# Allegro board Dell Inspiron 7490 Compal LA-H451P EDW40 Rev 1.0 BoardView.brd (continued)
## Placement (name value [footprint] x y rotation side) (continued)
PR2  15K_0402_1%  [R_0402]  119.53 12.51 0 top
PR3  100K_0402_1%  [R_0402]  117.88 12.51 0 top
PR4  10K_0402_1%  [R_0402]  117.84 15.18 270 top
PR5  2.2K_0402_5%  [R_0402]  116.4 15.61 180 top
PR37  100_0402_5%  [R_0402]  107.91 9.87 270 top
PR39  200_0402_5%  [R_0402]  108.82 11.7 270 top
PR41  10K_0402_1%  [R_0402]  109.59 10.79 90 top
PR42  100_0402_5%  [R_0402]  107.14 9.87 270 top
PR101  10K_0402_5%  [R_0402]  98.44 25.92 0 top
PR102  0_0402_5%  [R0402_0OHM]  103.85 27.47 0 top
PR103  1M_0402_5%  [R_0402]  104.76 25.94 180 top
PR104  1M_0402_5%  [R_0402]  103.85 26.7 0 top
PR105  100K_0402_5%  [R_0402]  99.35 26.71 180 top
PR301  0_0402_5%  [R_0402]  13.98 12.6 270 bottom
PR302  499K_0402_1%  [R_0402]  10.4 18.07 90 bottom
PR303  150K_0402_1%  [R_0402]  11.19 18.07 90 bottom
PR304  10K_0402_1%  [R_0402]  11.21 16.94 270 bottom
PR305  4.7_1206_5%  [R_1206]  17.27 14.01 0 top
PR306  1K_0402_5%  [R_0402]  14.4 18.99 270 bottom
PR307  150K_0402_1%  [R_0402]  12.73 18.99 270 bottom
PR308  150K_0402_1%  [R_0402]  11.97 18.07 90 bottom
PR501  150K_0201_5%  [R_0201]  11.89 27.1 0 bottom
PR502  0_0201_5%  [R_0201]  10.77 20.64 0 bottom
PR503  0_0201_5%  [R0201_0OHM]  14.89 20.99 90 bottom
PR504  0_0603_5%  [R_0603]  15.79 21.39 270 bottom
PR505  0_0402_5%  [R_0402]  12.08 21.43 270 bottom
PR506  348K_0402_1%  [R_0402]  14.72 19.8 180 bottom
PR507  499_0402_1%  [R_0402]  13.65 20.54 90 bottom
PR508  19.6K_0402_1%  [R_0402]  12.86 20.44 90 bottom
PR509  10K_0201_1%  [R_0201]  14.32 21.52 270 bottom
PR510  4.7_0805_5%  [R_0805]  18.44 20.92 90 top
PR521  0_0402_5%  [R0402_0OHM]  50.41 5.89 90 top
PR522  0_0402_5%  [R0402_0OHM]  51.17 5.89 90 top
PR523  2.2K_0402_5%  [R_0402]  51.93 5.89 90 top
PR524  0_0402_5%  [R0402_0OHM]  45.87 7.51 270 top
PR525  1M_0402_5%  [R_0402]  50.9 7.64 0 top
PR1802  150K_0201_5%  [R_0201]  73.35 22.62 0 top
PR1803  0_0603_5%  [R_0603]  67.73 22.18 90 top
PR1804  274K_0402_1%  [R_0402]  67.09 21.2 270 top
PR1805  499_0402_1%  [R_0402]  67.93 20.26 0 top
PR1806  40.2K_0402_1%  [R_0402]  67.93 19.48 0 top
PR1807  20K_0402_1%  [R_0402]  68.9 18.67 180 top
PR1808  4.7_0805_5%  [R_0805]  69.68 28.43 0 top
PR1809  0_0402_5%  [R_0402]  68.16 17.88 180 top
PR1810  1M_0402_5%  [R_0402]  68.15 17.09 180 top
PR1813  0_0402_5%  [R_0402]  68.93 17.89 270 top
PR1814  100K_0201_5%  [R_0201]  73.93 22.05 180 top
PR1815  100K_0402_1%  [R_0402]  112.15 17.64 0 top
PRA01  0_0201_5%  [R_0201]  139.88 20.39 270 bottom
PRA02  4.7_1206_5%  [R_1206]  142.41 23.9 0 top
PRB01  0.01_1206_1%  [R_1206_4P-D]  184.67 16.12 270 top
PRB02  1_0402_1%  [R_0402]  194.06 18.58 90 bottom
PRB03  1_0402_1%  [R_0402]  196.66 19.09 90 bottom
PRB04  0_0603_5%  [R0603_0OHM]  192.48 16.32 90 bottom
PRB05  442K_0402_1%  [R_0402]  189.47 23.87 0 bottom
PRB06  3.3_0603_1%  [R_0603]  198.15 19.97 270 bottom
PRB07  100K_0402_5%  [R_0402]  190.39 23.11 180 bottom
PRB08  1_0805_5%  [R_0805]  188.86 19.47 0 bottom
PRB09  4.7_0402_5%  [R_0402]  200.11 19.96 0 bottom
PRB10  0_0402_5%  [R0402_0OHM]  192.85 23.43 180 bottom
PRB11  499K_0402_1%  [R_0402]  192.41 20.36 180 bottom
PRB12  0.005_1206_1%  [R_1206_4P-D]  93.15 15.9 270 top
PRB13  0_0402_5%  [R_0402]  192.3 22.25 180 bottom
PRB14  0_0402_5%  [R_0402]  192.85 24.19 180 bottom
PRB15  4.7_0603_1%  [R_0603]  201.57 21.83 180 bottom
PRB16  0_0402_5%  [R_0402]  192.85 24.96 180 bottom
PRB17  4.7_1206_5%  [R_1206]  199.9 17 180 bottom
PRB18  4.7_1206_5%  [R_1206]  208.04 17 180 bottom
PRB19  75_0402_5%  [R_0402]  191.94 25.9 180 bottom
PRB20  768K_0402_1%  [R_0402]  189.37 25.18 0 bottom
PRB21  0_0402_5%  [R0402_0OHM]  200.49 24.59 0 bottom
PRB22  0_0402_5%  [R_0402]  192.85 26.9 180 bottom
PRB23  1M_0402_1%  [R_0402]  188.95 29.14 0 bottom
PRB24  100K_0402_1%  [R_0402]  193.99 27.68 90 bottom
PRB25  100K_0402_1%  [R_0402]  192.33 27.68 90 bottom
PRB26  93.1K_0402_1%  [R_0402]  195.06 27.7 90 bottom
PRB27  100K_0402_1%  [R_0402]  195.56 30.34 270 bottom
PRB29  0_0402_5%  [R0402_0OHM]  194.8 30.34 270 bottom
PRB30  0_0402_1%  [R_0402]  196.72 27.7 90 bottom
PRB31  0_0201_5%  [R0201_0OHM]  198.26 27.2 90 bottom
PRB32  1_0402_1%  [R_0402]  200.82 26.27 0 bottom
PRB33  8.25K_0201_1%  [R_0201]  197.7 27.2 90 bottom
PRB34  0_0201_5%  [R_0201]  199.13 28.9 90 bottom
PRB35  0_0201_5%  [R_0201]  198.57 28.9 90 bottom
PRB36  1_0402_1%  [R_0402]  200.67 27.97 0 bottom
PRB39  100_0402_5%  [R_0402]  199.81 28.2 270 bottom
PRB41  0_0201_5%  [R_0201]  190.79 20.64 90 bottom
PRB43  0_0201_5%  [R_0201]  188.29 29.06 90 bottom
PRB65  0_0603_5%  [R_0603]  101.25 8.3 270 top
PRB66  0_0603_5%  [R0603_0OHM]  101.99 5.81 180 top
PRF01  1_0402_1%  [R_0402]  119.24 43.22 180 bottom
PRF02  0_0402_5%  [R_0402]  118.33 41.5 0 bottom
PRF03  1M_0402_1%  [R_0402]  114.59 41.6 0 bottom
PRF04  100K_0402_1%  [R_0402]  119.21 44.05 180 bottom
PRF05  1.2K_0402_1%  [R_0402]  110.83 43.35 270 bottom
PRF06  4.53K_0402_1%  [R_0402]  111.82 42.41 270 bottom
PRG01  0_0201_5%  [R_0201]  200.42 35.24 270 bottom
PRG02  4.7_1206_5%  [R_1206]  195.68 44.12 90 bottom
PRH01  91K_0402_1%  [R_0402]  125.43 23.91 180 bottom
PRH02  51K_0201_1%  [R_0201]  125.01 24.62 180 bottom
PRH03  2.2_0603_5%  [R_0603]  126.91 24.23 90 bottom
PRH04  4.7_1206_5%  [R_1206]  133.15 22.8 0 top
PRH05  15K_0402_1%  [R_0402]  125.42 17.28 0 bottom
PRH06  20K_0402_1%  [R_0402]  126.32 18.09 180 bottom
PRH07  10K_0201_5%  [R_0201]  125.44 22.29 180 bottom
PRH08  0_0402_5%  [R_0402]  124.53 21.57 0 bottom
PRH09  0_0402_5%  [R_0402]  125.48 18.97 180 bottom
PRI01  0_0201_5%  [R_0201]  166.64 14.02 180 bottom
PRI02  4.7_1206_5%  [R_1206]  169.08 16.82 90 top
PRI03  0_0201_5%  [R_0201]  174.49 14.02 180 bottom
PRI04  4.7_1206_5%  [R_1206]  176.21 16.56 90 top
PRI05  0_0201_5%  [R_0201]  182.19 14.16 180 bottom
PRI06  4.7_1206_5%  [R_1206]  183.89 20.12 0 top
PRM15  1M_0402_1%  [R_0402]  191.45 64.92 180 bottom
PRM17  0_0402_5%  [R_0402]  189.76 64 90 bottom
PRM18  0_0402_1%  [R_0402]  192.64 65.01 270 bottom
PRM19  75_0402_5%  [R_0402]  196.58 64.1 90 bottom
PRM20  2.2_0603_5%  [R_0603]  196.81 66.32 90 bottom
PRM21  100K_0402_1%  [R_0402]  193.4 65.01 270 bottom
PRM22  0_0402_5%  [R_0402]  191.9 64.16 180 bottom
PRM23  1M_0402_1%  [R_0402]  190.08 65.81 180 bottom
PRM24  4.7_0805_5%  [R_0805]  198.09 70.02 90 top
PRM25  100K_0402_1%  [R_0402]  194.16 64.1 90 bottom
PRM26  100K_0402_5%  [R_0402]  198.1 63.02 270 bottom
PRM27  5.1_0402_1%  [R_0402]  192.07 72.36 180 bottom
PRV03  1M_0402_1%  [R_0402]  37.11 68.02 270 top
PRV20  0_0402_5%  [R0402_0OHM]  55.35 76.11 0 bottom
PRV21  0_0402_5%  [R0402_0OHM]  52.27 76.14 270 bottom
PRV22  0_0402_5%  [R0402_0OHM]  53.8 76.14 270 bottom
PRV23  10K_0402_1%  [R_0402]  53.04 75.22 90 bottom
PRV24  4.7_1206_5%  [R_1206]  57.14 76.7 0 top
PRV25  0_0402_5%  [R_0402]  54.56 76.14 270 bottom
PRV26  0_0402_5%  [R0402_0OHM]  55.29 68.62 0 bottom
PRV27  0_0402_5%  [R0402_0OHM]  52.21 68.67 270 bottom
PRV28  0_0402_5%  [R0402_0OHM]  53.73 68.67 270 bottom
PRV29  10K_0402_1%  [R_0402]  52.97 67.75 90 bottom
PRV30  4.7_1206_5%  [R_1206]  58.9 65.01 0 top
PRV31  0_0402_5%  [R_0402]  54.5 68.67 270 bottom
PRV32  133K_0201_1%  [R_0201]  43.5 64 0 top
PRV33  100_0402_5%  [R_0402]  43.34 61.82 0 top
PRV34  2M_0402_5%  [R_0402]  43.34 63.34 0 top
PRV35  1K_0402_5%  [R_0402]  42.1 66.74 0 top
PRV36  10K_0402_5%  [R_0402]  35.71 63.72 0 top
PRV37  10K_0402_5%  [R_0402]  35.62 60.54 0 top
PRV38  10K_0402_5%  [R_0402]  36.39 64.51 90 top
PRV39  1K_0402_5%  [R_0402]  42.1 67.5 0 top
PRV40  4.7_0402_5%  [R_0402]  39.39 67.1 90 top
PRV41  10K_0402_5%  [R_0402]  37.71 60.72 270 top
PRV42  100_0402_5%  [R_0402]  43.47 59.66 90 top
PRV43  10K_0402_5%  [R_0402]  38.63 68.02 270 top
PRV44  0_0402_5%  [R0402_0OHM]  43.34 62.58 0 top
PRV45  49.9K_0402_1%  [R_0402]  41.91 60.34 270 top
PRV46  0_0402_5%  [R0402_0OHM]  39.36 59.8 90 top
PRV47  0_0402_5%  [R0402_0OHM]  42.68 60.57 270 top
PRV48  0_0402_5%  [R0402_0OHM]  35.61 65.42 270 top
PRV49  10K_0402_5%  [R_0402]  35.62 61.3 0 top
PRV50  10K_0402_5%  [R_0402]  35.63 62.57 0 top
PRV51  0_0402_5%  [R0402_0OHM]  37.87 68.02 270 top
PRW12  4.7_1206_5%  [R_1206]  70.73 55.06 0 bottom
PRW13  28K_0402_1%  [R_0402]  63.4 55.91 0 top
PRW14  0_0603_5%  [R_0603]  71.02 53.75 0 top
PRW16  22.1K_0402_1%  [R_0402]  64.29 56.75 180 top
PRW17  0_0402_5%  [R_0402]  63.4 57.66 0 top
PRW18  100K_0402_5%  [R_0402]  66.49 58.96 270 top
PRW19  0_0402_5%  [R_0402]  63.42 59.7 0 top
PRW21  1K_0402_5%  [R_0402]  62.57 55.91 270 top
PRW22  1M_0402_1%  [R_0402]  62.51 59.53 270 top
PRW23  0_0402_5%  [R_0402]  64.3 58.64 180 top
PRW24  0_0402_5%  [R0402_0OHM]  61.87 53.95 270 top
PRZ02  10K_0402_1%  [R_0402]  164.02 18.52 90 bottom
PRZ03  10K_0402_1%  [R_0402]  162.42 18.4 90 bottom
PRZ04  10K_0402_1%  [R_0402]  164.52 17.31 180 bottom
PRZ05  10K_0402_1%  [R_0402]  160.92 16.51 90 bottom
PRZ06  0_0402_5%  [R_0402]  160.16 17.43 270 bottom
PRZ07  0_0201_5%  [R_0201]  162.96 16.81 90 bottom
PRZ08  0_0201_5%  [R_0201]  161.75 19.27 270 bottom
PRZ09  0_0201_5%  [R_0201]  163.34 19.27 270 bottom
PRZ10  0_0402_5%  [R0402_0OHM]  161.71 20.77 0 bottom
PRZ11  49.9_0402_1%  [R_0402]  161.75 24.95 180 bottom
PRZ12  0_0201_5%  [R0201_0OHM]  160.95 22.96 0 bottom
PRZ13  10_0402_1%  [R_0402]  161.76 23.97 180 bottom
PRZ14  0_0201_5%  [R0201_0OHM]  161.44 27.34 90 bottom
PRZ15  10K_0201_1%  [R_0201]  162 27.92 270 bottom
PRZ16  8.25K_0201_1%  [R_0201]  152.14 16.38 90 bottom
PRZ17  0_0402_5%  [R_0402]  153.79 17.42 270 bottom
PRZ18  0_0201_5%  [R_0201]  161.58 17.26 270 bottom
PRZ19  10K_0201_1%  [R_0201]  162.14 16.68 90 bottom
PRZ20  61.9K_0402_1%  [R_0402]  160.78 28.34 270 bottom
PRZ21  10K_0402_1%  [R_0402]  163.78 21.26 270 bottom
PRZ22  45.3_0402_1%  [R_0402]  163.47 24.39 180 bottom
PRZ23  75_0402_1%  [R_0402]  162.87 21.67 180 bottom
PRZ24  100_0402_1%  [R_0402]  163.47 23.62 180 bottom
PRZ26  75_0402_5%  [R_0402]  164.52 20.36 0 bottom
PRZ27  0_0201_5%  [R_0201]  162.5 25.06 0 bottom
PRZ28  0_0201_5%  [R_0201]  161.79 22.35 0 bottom
PRZ29  0_0201_5%  [R_0201]  165.24 23.25 90 bottom
PRZ30  53.6K_0402_1%  [R_0402]  155.34 29.1 0 bottom
PRZ31  120K_0402_1%  [R_0402]  157.47 28.09 270 bottom
PRZ32  620K_0402_1%  [R_0402]  159.12 28.09 270 bottom
PRZ33  0_0402_5%  [R0402_0OHM]  156.53 17.3 270 bottom
PRZ34  49.9K_0402_1%  [R_0402]  155.76 17.3 270 bottom
PRZ35  8.06K_0402_1%  [R_0402]  153.58 27.07 0 bottom
PRZ36  100K_0402_1%  [R_0402]  154.49 27.83 180 bottom
PRZ38  0_0402_5%  [R0402_0OHM]  155.25 28.01 270 bottom
PRZ39  0_0402_5%  [R0402_0OHM]  156.01 28.01 270 bottom
PRZ40  0_0402_5%  [R0402_0OHM]  152.83 27.96 270 bottom
PRZ41  0_0402_5%  [R0402_0OHM]  152.06 27.96 270 bottom
PRZ42  100K_0201_1%  [R_0201]  150.9 26.14 270 bottom
PRZ43  2.49K_0402_1%  [R_0402]  151.56 25.4 90 bottom
PRZ44  0_0402_5%  [R0402_0OHM]  150.37 24.6 0 bottom
PRZ45  0_0402_5%  [R0402_0OHM]  150.37 23.84 0 bottom
PRZ46  100K_0201_1%  [R_0201]  150.85 22.87 270 bottom
PRZ47  1.43K_0402_1%  [R_0402]  151.51 22.12 90 bottom
PRZ48  1.5K_0402_1%  [R_0402]  151.94 18.36 90 bottom
PRZ49  1.5K_0402_1%  [R_0402]  150.75 19.02 180 bottom
PRZ50  1.5K_0402_1%  [R_0402]  150.75 19.79 180 bottom
PRZ51  1.5K_0402_1%  [R_0402]  150.75 20.55 180 bottom
PRZ52  1.5K_0402_1%  [R_0402]  150.75 21.32 180 bottom
PRZ53  4.7_0402_5%  [R_0402]  157.3 16.51 90 bottom
PRZ54  0_0402_5%  [R_0402]  162.67 28.09 270 bottom
PRZ55  2M_0402_5%  [R_0402]  149.72 16.51 90 bottom
PRZ56  133K_0402_1%  [R_0402]  151.37 17.3 270 bottom
PU301  -  [SY8386BRHC_QFN16_2P5X2P5]  14.45 14.2 90 bottom
PU501  -  [NB502GQ-Z_QFN16_3X3]  13.11 23.9 0 bottom
PU1801  -  [NB691GG-Z_QFN11_2X2]  70.89 20.32 90 top
PUA01  -  [MP86902-BGLT-Z_TQFN21-15_3X4]  142.74 20.49 270 bottom
PUB01  -  [ISL9538BHRTZ-T_TQFN32_4X4]  198.41 25.27 180 bottom
PUF01  RTQ2522AGQW(2)_WDFN10_3X3  [RTQ2522AGQW_WDFN10_3X3]  116.93 44.71 270 bottom
PUG01  -  [MP86902-BGLT-Z_TQFN21-15_3X4]  200.54 37.5 0 bottom
PUH01  -  [RT6243BGQVF_VQFN18_3P5X3P5]  127.86 22.81 270 bottom
PUI01  -  [MP86902-BGLT-Z_TQFN21-15_3X4]  168.77 13.68 270 bottom
PUI02  -  [MP86902-BGLT-Z_TQFN21-15_3X4]  176.47 13.68 270 bottom
PUI03  -  [MP86902-BGLT-Z_TQFN21-15_3X4]  184.23 13.68 270 bottom
PUM01  -  [NB685AGQ-Z_QFN16_3X3]  192.94 68.12 0 bottom
PUV01  -  [MP2988GQ-0010-Z_QFN20_3X3]  38.56 64.46 0 top
PUV02  -  [MP86902-BGLT-Z_TQFN21-15_3X4]  55.99 73.04 180 bottom
PUV03  -  [MP86902-BGLT-Z_TQFN21-15_3X4]  56.01 65.46 180 bottom
PUW01  -  [SY8286RAC_QFN20_3X3]  69.58 54.18 180 top
PUZ01  -  [MP2979AGQKT-0038-Z_TQFN48_6X6]  153.2 20.48 0 bottom
Q3  -  [DMN5L06TK-7_SOT523-3]  37.7 45.29 0 top
Q5  -  [SI1553CDL-T1-GE3_SC70-6]  119.79 9.39 90 top
Q7  -  [L2N7002WT1G_SC-70-3]  33.93 8.99 270 top
Q8  -  [L2N7002WT1G_SC-70-3]  117 7.04 90 top
Q9  -  [L2N7002WT1G_SC-70-3]  65.67 8.75 90 top
Q10  L2N7002DW1T1G_SC88-6  [DMN66D0LDW-7_SOT363-6]  114.53 8.2 180 top
Q11  L2N7002DW1T1G_SC88-6  [DMN66D0LDW-7_SOT363-6]  33.15 70.88 270 top
Q12  -  [LMUN5111T1G_SC70-3]  63.53 6.67 270 top
Q13  -  [MMBT3904WT1G_SC70-3]  196.49 30.73 180 bottom
Q15  L2N7002DW1T1G_SC88-6  [DMN66D0LDW-7_SOT363-6]  39.15 42.98 180 top
Q16  L2N7002DW1T1G_SC88-6  [DMN66D0LDW-7_SOT363-6]  39.19 45.98 270 top
Q17  -  [NTK3139PT1G_SOT723-3]  61.34 24.12 0 top
Q18  -  [L2N7002WT1G_SC-70-3]  60.51 20.15 180 top
Q19  -  [L2N7002WT1G_SC-70-3]  63.69 33.07 0 top
Q26  -  [L2N7002WT1G_SC-70-3]  27.85 5.96 90 top
Q27  -  [L2N7002WT1G_SC-70-3]  97.14 9.32 180 bottom
Q28  -  [DMN2400UV-7_SOT-563-6]  70.81 71.62 270 top
Q29  -  [DMN2400UV-7_SOT-563-6]  61.31 16.8 0 top
Q30  -  [PMDXB600UNE_DFN1010B-6]  38.75 31.84 90 top
Q31  -  [LMUN5111T1G_SC70-3]  35.51 39.4 180 top
Q32  -  [LMUN5111T1G_SC70-3]  34.06 44.63 90 top
QC1  -  [DMN2400UV-7_SOT-563-6]  124.43 53.66 90 bottom
QE11  -  [L2N7002WT1G_SC-70-3]  58.86 16.14 180 top
QN3  BSS138W_SOT-323-3-X  [L2N7002WT1G_SC-70-3]  54.62 40.08 180 top
QN4  -  [DMN2400UV-7_SOT-563-6]  59.55 37.3 0 top
QN7  -  [DMN2400UV-7_SOT-563-6]  56.73 37.3 0 top
QN8  -  [DMN2400UV-7_SOT-563-6]  61.95 37.36 270 top
QV2  PJT138KA_SOT363-6  [DMN66D0LDW-7_SOT363-6]  111.73 73 180 bottom
QV3  -  [DMN5L06TK-7_SOT523-3]  115.2 42.61 45 top
QV8  PJT138KA 2N SOT363-6  [DMN66D0LDW-7_SOT363-6]  107.32 74.54 90 bottom
QV18  -  [MMDT3906_SOT363-6]  32.81 73.29 270 top
QV19  -  [LMBT3904WT1G_SC70-3]  32.58 76.8 270 top
QV21  -  [LMBT3904WT1G_SC70-3]  30.67 77.34 180 top
QV50  -  [DMN5L06TK-7_SOT523-3]  95.57 64.01 90 top
QV144  PJT138K_SOT363-6  [2N7002DW-7-F_SOT363-6]  116.73 55.37 270 top
QV145  PJT138K_SOT363-6  [2N7002DW-7-F_SOT363-6]  93.97 33.48 0 top
QV146  PJT138K_SOT363-6  [2N7002DW-7-F_SOT363-6]  113.93 73 0 top
QV147  PJT138KA_SOT363-6  [DMN66D0LDW-7_SOT363-6]  114.12 73 180 bottom
QV150  PJT138KA 2N SOT363-6  [DMN66D0LDW-7_SOT363-6]  112.84 48.26 225 top
QV151  PJT138K_SOT363-6  [2N7002DW-7-F_SOT363-6]  121.73 47.44 90 top
QV152  PJT138K_SOT363-6  [2N7002DW-7-F_SOT363-6]  80.85 32.25 90 top
QZ3  -  [LMUN5111T1G_SC70-3]  38.19 10.83 270 top
QZ21  -  [LMBT3904WT1G_SC70-3]  37.61 12.71 0 top
R5  100K_0201_5%  [R_0201]  97.04 10.31 0 bottom
R6  100K_0201_5%  [R_0201]  96.41 10.5 90 bottom
R10  0_0201_5%  [R_0201-NPM]  32.19 66.37 90 bottom
R12  0_0201_5%  [R_0201-NPM]  31.61 66.37 90 bottom
R17  100K_0201_5%  [R_0201]  46.11 53.52 90 top
R25  0_0201_5%  [R0201_0OHM]  3.3 75.29 0 bottom
R26  10K_0201_5%  [R_0201]  36.38 42.46 0 top
R27  1.3K_0402_1%  [R_0402]  13.61 58.69 90 bottom
R28  1.3K_0402_1%  [R_0402]  13.61 57.95 270 bottom
R30  100K_0201_5%  [R_0201]  40.35 43.14 90 top
R31  100K_0201_5%  [R_0201]  40.98 43.14 90 top
R32  0_0201_5%  [R0201_0OHM]  115.53 8.32 270 top
R33  0_0201_5%  [R0201_0OHM]  115.46 6.94 270 top
R36  4.7K_0201_5%  [R_0201]  113.33 4.86 90 top
R37  4.7K_0201_5%  [R_0201]  114.34 9.01 0 top
R38  17.4K_0201_1%  [R_0201]  36.25 8.7 90 top
R39  100_0402_5%  [R_0402]  116.89 9.64 270 top
R40  10K_0201_5%  [R_0201]  36.81 8.7 90 top
R41  20K_0201_5%  [R_0201]  119.68 11.53 180 top
R42  10K_0201_5%  [R_0201]  120.43 7.99 180 top
R43  2.2K_0201_5%  [R_0201]  116.07 6.36 90 top
R45  2.2K_0201_5%  [R_0201]  116.12 8.98 180 top
R46  100K_0201_5%  [R_0201]  121.01 9.64 0 top
R47  100K_0201_5%  [R_0201]  38.87 28.63 0 top
R48  1K_0402_5%  [R_0402]  64.6 7.74 270 top
R49  2.2K_0201_5%  [R_0201]  32.28 69.34 180 top
R50  2.2K_0201_5%  [R_0201]  36.13 70.2 270 top
R53  0_0201_5%  [R0201_0OHM]  135.95 50.41 270 top
R54  14K_0402_1%  [R_0402]  133.49 42.68 180 top
R55  7.5K_0201_1%  [R_0201]  131.69 50.79 270 top
R63  10K_0201_5%  [R_0201]  60.62 26.66 180 top
R64  1M_0201_5%  [R_0201]  60.24 23.38 90 top
R65  100K_0201_5%  [R_0201]  60.24 24.57 90 top
R75  100K_0201_5%  [R_0201]  58.45 36.13 180 top
R76  2.2K_0201_5%  [R_0201]  49.17 33.66 90 top
R77  100K_0201_5%  [R_0201]  34.01 67.02 270 bottom
R86  4.7K_0201_5%  [R_0201]  41.04 53.05 0 top
R87  4.7K_0201_5%  [R_0201]  41.04 52.49 0 top
R88  10K_0201_5%  [R_0201]  41.04 51.93 0 top
R89  100K_0201_5%  [R_0201]  37.95 40.27 0 top
R90  10K_0201_5%  [R_0201]  24.5 75.46 0 top
R91  0_0201_5%  [R0201_0OHM]  35.52 73.15 270 top
R241  0_0201_5%  [R_0201]  125.01 14.71 0 top
R242  100K_0201_5%  [R_0201]  125.6 14.15 180 top
R256  0_0402_5%  [R0402_0OHM]  95.75 11.41 270 bottom
R270  33_0201_5%  [R_0201]  36.09 67.11 0 bottom
R271  33_0201_5%  [R_0201]  35.48 67.11 180 bottom
R272  33_0201_5%  [R_0201]  36.09 66.5 0 bottom
R273  33_0201_5%  [R_0201]  35.48 66.5 180 bottom
R1014  10K_0201_5%  [R_0201]  39.53 77.11 90 top
R4931  1K_0603_1%  [R_0603]  38.29 77.67 270 top
R6902  0_0603_5%  [R0603_0OHM]  103.58 33.9 0 top
R6906  0_0402_5%  [R0402_0OHM]  51.42 42.41 90 top
R6907  0_0402_5%  [R0402_0OHM]  120.75 11.19 270 top
R6908  0_0201_5%  [R_0201]  14.45 71.31 180 top
RB21  560_0201_1%  [R_0201]  26.35 5.22 180 bottom
RB22  560_0201_1%  [R_0201]  25.74 4.04 90 bottom
RC1  1K_01005_1%  [R_01005]  166.79 37.68 270 top
RC2  1K_01005_1%  [R_01005]  151.07 33.37 90 bottom
RC4  24.9_0201_1%  [R_0201]  159.08 38.19 270 top
RC5  10K_01005_1%  [R_01005]  135.56 57.15 270 top
RC6  10K_01005_1%  [R_01005]  134.98 36.52 90 top
RC8  2.2K_01005_1%  [R_01005]  141.62 40.99 180 top
RC9  2.2K_01005_1%  [R_01005]  139.56 33.68 270 bottom
RC10  100K_01005_1%  [R_01005]  145.54 57.09 90 top
RC11  100K_01005_1%  [R_01005]  144.89 50.78 90 top
RC12  100K_01005_1%  [R_01005]  136.82 39.42 0 top
RC13  100K_01005_1%  [R_01005]  132.65 41.65 180 bottom
RC15  49.9_0201_1%  [R_0201]  146.63 51.14 270 top
RC16  49.9_0201_1%  [R_0201]  143.48 49.58 0 top
RC17  200_0201_1%  [R_0201]  148.33 51.88 270 top
RC18  80.6_0201_1%  [R_0201]  147.43 51.16 270 top
RC19  200K_01005_1%  [R_01005]  183.55 49.27 180 bottom
RC20  162_0201_1%  [R_0201]  147.71 53.11 270 top
RC21  24.9_0201_1%  [R_0201]  130.58 60.26 270 bottom
RC22  24.9_0201_1%  [R_0201]  133.65 61.3 0 bottom
RC23  24.9_0201_1%  [R_0201]  134.23 55.08 0 top
RC24  24.9_0201_1%  [R_0201]  136.8 54.28 90 top
RC25  24.9_0201_1%  [R_0201]  131.15 57.9 90 bottom
RC26  33_0201_5%  [R_0201]  143.41 56.18 0 top
RC31  4.7K_0201_5%  [R_0201]  131.52 61.47 180 bottom
RC33  1K_01005_1%  [R_01005]  137.99 43.55 0 top
RC34  1K_01005_1%  [R_01005]  140.48 44.55 270 top
RC35  100K_0201_5%  [R_0201]  135.66 54.87 270 top
RC36  100K_0201_5%  [R_0201]  136.23 54.87 270 top
RC37  100K_0201_5%  [R_0201]  130.58 58.49 270 bottom
RC38  4.7K_01005_5%  [R_01005]  137.77 44.64 180 top
RC39  15_0201_1%  [R_0201]  51.82 13.43 180 top
RC40  15_0201_1%  [R_0201]  40.63 13.43 0 top
RC41  15_0201_1%  [R_0201]  40.63 12.22 0 top
RC42  15_0201_1%  [R_0201]  40.63 14.7 0 top
RC43  15_0201_1%  [R_0201]  51.33 11.55 90 top
RC44  4.7K_01005_5%  [R_01005]  139.38 43.7 270 top
RC46  4.7K_01005_5%  [R_01005]  141.66 58.44 90 top
RC47  33_01005_1%  [R_01005]  146.77 60.29 180 bottom
RC48  33_0201_5%  [R_0201]  147.87 60.99 270 bottom
RC49  33_01005_1%  [R_01005]  148.83 60.67 270 bottom
RC50  1K_01005_1%  [R_01005]  148.37 60.67 270 bottom
RC51  4.7K_01005_5%  [R_01005]  149.47 60.31 90 bottom
RC52  10K_01005_1%  [R_01005]  137.45 46.34 180 top
RC53  10K_01005_1%  [R_01005]  131.03 44.65 0 bottom
RC54  200_0201_1%  [R_0201]  137.46 56.62 0 top
RC55  10K_01005_1%  [R_01005]  137.1 45.84 0 top
RC56  10K_01005_1%  [R_01005]  132.63 44.64 180 bottom
RC57  4.7K_01005_5%  [R_01005]  141.12 58.79 270 top
RC58  100K_01005_1%  [R_01005]  137.91 60.92 270 bottom
RC60  150_0201_1%  [R_0201]  132.57 54.65 90 bottom
RC61  10K_01005_1%  [R_01005]  141.19 45.81 180 top
RC62  4.7K_01005_5%  [R_01005]  140.58 50.05 270 top
RC64  200_0201_1%  [R_0201]  137.46 45.3 0 top
RC65  4.7K_01005_5%  [R_01005]  131.2 51.19 90 bottom
RC68  10K_01005_1%  [R_01005]  138.85 52.19 180 top
RC69  10K_01005_1%  [R_01005]  131.05 43.65 0 bottom
RC70  10K_01005_1%  [R_01005]  137.23 43.5 180 top
RC71  10K_01005_1%  [R_01005]  132.63 43.65 180 bottom
RC72  10K_01005_1%  [R_01005]  136.4 43.33 270 top
RC73  75K_01005_1%  [R_01005]  138.75 52.97 90 top
RC74  75K_01005_1%  [R_01005]  136.18 55.62 0 top
RC75  100K_01005_1%  [R_01005]  123.47 51.34 0 bottom
RC77  20K_01005_1%  [R_01005]  143.9 60.29 0 bottom
RC78  10K_01005_1%  [R_01005]  138.86 56.01 270 top
RC79  0_01005_5%  [R01005_0OHM]  146.56 55.8 90 top
RC82  20K_01005_1%  [R_01005]  126.31 51.67 90 bottom
RC83  60.4_0201_1%  [R_0201]  138.96 33.6 180 bottom
RC86  10K_01005_1%  [R_01005]  132.31 30.98 0 bottom
RC87  330K_01005_1%  [R_01005]  143.47 60.29 180 bottom
RC88  10K_01005_1%  [R_01005]  139.93 56.01 270 top
RC89  0_0201_5%  [R_0201]  136.99 32.29 270 bottom
RC90  200K_01005_1%  [R_01005]  136.45 31.67 270 bottom
RC91  0_0201_5%  [R_0201]  137.57 31.06 180 bottom
RC92  1K_0201_5%  [R_0201]  145.02 52.86 90 top
RC93  10K_01005_1%  [R_01005]  144.87 58.41 270 top
RC94  100K_01005_1%  [R_01005]  138.33 69.86 180 top
RC95  10M_0201_5%  [R_0201]  131.12 55.44 270 bottom
RC96  10K_01005_1%  [R_01005]  144.41 58.05 90 top
RC98  100K_01005_1%  [R_01005]  145.45 52.33 0 top
RC99  62_01005_1%  [R_01005]  151.53 33.37 90 bottom
RC100  10K_01005_1%  [R_01005]  136.59 41.9 0 top
RC102  0_01005_5%  [R01005_0OHM]  127.74 51.48 270 bottom
RC103  4.7K_01005_5%  [R_01005]  146.25 51.87 180 top
RC104  4.7K_01005_5%  [R_01005]  146.05 51.14 270 top
RC105  1M_01005_1%  [R_01005]  120.1 52.6 90 bottom
RC106  10K_01005_1%  [R_01005]  140.45 51.44 90 top
RC107  10K_01005_1%  [R_01005]  132.69 49.99 180 bottom
RC108  4.7K_01005_5%  [R_01005]  140.67 47.17 90 top
RC110  10K_01005_1%  [R_01005]  137.02 50.33 270 top
RC112  4.7K_01005_5%  [R_01005]  143.01 53.99 180 top
RC113  10K_01005_1%  [R_01005]  140.32 42.81 90 top
RC114  10K_01005_1%  [R_01005]  136.49 50.56 270 top
RC115  4.7K_01005_5%  [R_01005]  143.01 54.44 180 top
RC117  10K_01005_1%  [R_01005]  136.18 49.01 180 top
RC118  10K_01005_1%  [R_01005]  130.34 49.27 180 bottom
RC119  10K_01005_1%  [R_01005]  135.39 49.01 180 top
RC120  10K_01005_1%  [R_01005]  129.55 49.27 180 bottom
RC122  20K_01005_1%  [R_01005]  138.29 46.93 90 top
RC123  113_0201_1%  [R_0201]  141.45 33.62 270 bottom
RC124  10K_0201_5%  [R_0201]  140.84 40.33 270 top
RC125  10K_0201_5%  [R_0201]  142.13 33.62 270 bottom
RC126  100_0201_1%  [R_0201]  140.84 38.57 90 top
RC127  10K_01005_1%  [R_01005]  132.65 39.74 180 bottom
RC130  0_0201_5%  [R_0201]  131.23 34.93 90 bottom
RC132  0_0402_5%  [R0402_0OHM]  142.47 58.81 0 top
RC133  0_0402_5%  [R_0402]  142.14 49.87 180 top
RC134  56_0201_5%  [R_0201]  168.12 31.22 180 bottom
RC135  220_0201_5%  [R_0201]  167.53 32.39 270 bottom
RC136  100_0201_1%  [R_0201]  167.96 30.34 180 bottom
RC158  10K_0201_5%  [R_0201]  36.96 43.05 180 top
RC160  499_01005_1%  [R_01005]  166.78 36.87 0 top
RC162  20K_01005_1%  [R_01005]  140.13 47.93 270 top
RC164  100_0201_1%  [R_0201]  150.14 39.22 0 top
RC165  100_0201_1%  [R_0201]  151.61 38.69 90 top
RC167  100_0201_1%  [R_0201]  159.88 33.04 90 bottom
RC168  100_0201_1%  [R_0201]  161.21 33.63 270 bottom
RC169  100_0201_1%  [R_0201]  182.9 33.08 180 bottom
RC170  100_0201_1%  [R_0201]  182.32 34.3 0 bottom
RC187  100K_0201_5%  [R_0201]  131.15 59.68 90 bottom
RC188  10K_01005_1%  [R_01005]  132.65 40.27 180 bottom
RC189  10K_01005_1%  [R_01005]  137.12 38.7 180 top
RC190  10K_01005_1%  [R_01005]  132.65 38.7 180 bottom
RC191  10K_01005_1%  [R_01005]  137.87 42.16 0 top
RC192  15_0201_1%  [R_0201]  125.86 45.43 180 bottom
RC193  15_0201_1%  [R_0201]  126.21 44.82 180 bottom
RC194  15_0201_1%  [R_0201]  126 40.65 180 bottom
RC195  15_0201_1%  [R_0201]  125.98 40.03 180 bottom
RC196  1K_01005_1%  [R_01005]  136.61 43.96 0 top
RC197  1K_01005_1%  [R_01005]  136.61 44.48 0 top
RC198  1K_01005_1%  [R_01005]  137.87 42.7 0 top
RC199  1K_01005_1%  [R_01005]  138.93 43.7 270 top
RC200  10K_01005_1%  [R_01005]  131.03 45.41 0 bottom
RC201  10K_01005_1%  [R_01005]  132.62 45.4 180 bottom
RC203  10K_0201_5%  [R_0201]  136.47 42.41 0 top
RC205  100K_01005_1%  [R_01005]  140.54 52.3 0 top
RC206  10K_01005_1%  [R_01005]  139.4 56.01 270 top
RC207  1K_01005_1%  [R_01005]  139.03 49.87 90 top
RC208  1K_01005_1%  [R_01005]  138.58 49.87 90 top
RC211  100K_01005_1%  [R_01005]  137.4 63.05 180 bottom
RC213  100K_01005_1%  [R_01005]  136.92 61.36 90 bottom
RC215  10K_01005_1%  [R_01005]  131.05 48.08 0 bottom
RC216  10K_01005_1%  [R_01005]  132.64 48.08 180 bottom
RC217  10K_01005_1%  [R_01005]  131.05 48.75 0 bottom
RC218  10K_01005_1%  [R_01005]  132.64 48.74 180 bottom
RC219  10K_01005_1%  [R_01005]  131.05 47.41 0 bottom
RC220  10K_01005_1%  [R_01005]  132.65 47.41 180 bottom
RC221  10K_01005_1%  [R_01005]  131.05 46.82 0 bottom
RC222  10K_01005_1%  [R_01005]  132.65 46.76 180 bottom
RC223  10K_01005_1%  [R_01005]  131.05 46.09 0 bottom
RC224  10K_01005_1%  [R_01005]  132.63 46.1 180 bottom
RC225  100K_01005_1%  [R_01005]  138.6 46.32 270 top
RC226  100K_01005_1%  [R_01005]  137.76 46.93 90 top
RC227  100K_0201_5%  [R_0201]  137.76 47.82 180 top
RC228  100K_0201_5%  [R_0201]  138.68 45.42 0 top
RC230  10K_01005_1%  [R_01005]  131.66 51.19 90 bottom
RC238  0_0201_5%  [R0201_0OHM]  144.22 9.03 180 top
RC239  51_0201_5%  [R_0201]  170.93 37.59 90 top
RC240  51_0201_5%  [R_0201]  170.2 37.56 90 top
RC241  1K_0201_5%  [R_0201]  135.03 54.47 180 top
RC242  100_0201_5%  [R_0201]  169.62 37.56 90 top
RC243  1K_0201_5%  [R_0201]  137.57 54.57 270 top
RC244  51_0201_5%  [R_0201]  171.53 37.39 90 top
RC245  0_0201_5%  [R0201_0OHM]  128.75 12.83 0 top
RC246  0_0201_5%  [R0201_0OHM]  130.52 12.84 180 top
RC247  0_0201_5%  [R0201_0OHM]  131.94 13.15 270 top
RC248  0_0201_5%  [R0201_0OHM]  139.35 11.42 90 top
RC249  0_0402_5%  [R0402_0OHM]  138.04 11.22 90 top
RC250  1K_0201_5%  [R_0201]  131.39 13.15 270 top
RC251  0_0402_5%  [R0402_0OHM]  136.75 13.81 270 top
RC253  1.5K_0201_5%  [R_0201]  122.53 11.05 270 top
RC256  1K_0201_5%  [R_0201]  145.75 6.14 180 top
RC258  51_0201_5%  [R_0201]  170.39 38.85 180 top
RC262  10K_01005_1%  [R_01005]  140.47 56.01 270 top
RC263  0_0201_5%  [R0201_0OHM]  167.98 29.72 180 bottom
RC264  0_0201_5%  [R0201_0OHM]  164.14 29.24 270 bottom
RC370  0_0201_5%  [R_0201]  144.22 9.58 180 top
RC381  100K_0201_5%  [R_0201]  120.59 55.58 90 bottom
RC387  0_0201_5%  [R_0201]  124.9 55.44 0 bottom
RC388  0_0201_5%  [R_0201]  124.86 52.88 180 bottom
RC390  0_0201_5%  [R_0201]  120.59 54.36 90 bottom
RC395  10K_01005_1%  [R_01005]  130.49 43.68 180 bottom
RC405  1K_0201_1%  [R_0201]  172.91 31.4 90 bottom
RC406  1K_0201_1%  [R_0201]  171.51 31.37 90 bottom
RC407  1K_0201_1%  [R_0201]  172.81 33.02 90 bottom
RC408  1K_0201_1%  [R_0201]  179.12 32.63 180 bottom
RC409  1K_0201_1%  [R_0201]  174.33 33.02 90 bottom
RC410  1K_0201_1%  [R_0201]  175.63 31.45 90 bottom
RC411  1K_0201_1%  [R_0201]  174.38 31.45 90 bottom
RC412  1K_0201_1%  [R_0201]  172.2 33.02 90 bottom
RC413  1K_0201_1%  [R_0201]  173.57 31.4 90 bottom
RC414  1K_0201_1%  [R_0201]  172.25 31.37 90 bottom
RC415  1K_0201_1%  [R_0201]  173.44 33.02 90 bottom
RC416  1K_0201_1%  [R_0201]  177.93 32.63 180 bottom
RC417  1K_0201_1%  [R_0201]  174.99 33.02 90 bottom
RC418  1K_0201_1%  [R_0201]  176.16 33.02 90 bottom
RC419  1K_0201_1%  [R_0201]  174.99 31.45 90 bottom
RC420  0_0201_5%  [R_0201]  182.32 56 0 bottom
RC433  100K_0201_5%  [R_0201]  123.64 54.13 270 bottom
RC436  100K_0201_5%  [R_0201]  161.91 52.57 0 top
RC504  100K_01005_1%  [R_01005]  131.51 38.7 180 bottom
RC513  100K_01005_1%  [R_01005]  144.44 56.83 90 top
RC514  100K_01005_1%  [R_01005]  145.52 54 270 top
RC516  10K_01005_1%  [R_01005]  140.91 51.84 270 top
RC517  10K_01005_1%  [R_01005]  131.43 42.97 180 bottom
RC518  100K_01005_1%  [R_01005]  141.45 57.1 180 top
RC523  0_01005_5%  [R01005_0OHM]  182.36 49.27 0 bottom
RC524  15_0201_1%  [R_0201]  53.24 24.54 180 top
RC525  15_0201_1%  [R_0201]  53.12 23.56 180 top
RC526  15_0201_1%  [R_0201]  53.14 21.25 180 top
RC527  15_0201_1%  [R_0201]  53.14 21.83 180 top
RC528  15_0201_1%  [R_0201]  53.13 22.99 180 top
RC529  1K_0201_5%  [R_0201]  137.48 12.88 90 top
RC531  1K_0201_5%  [R_0201]  138.77 12.73 0 top
RC533  100K_0201_5%  [R_0201]  142.04 12 270 top
RC535  1K_0201_5%  [R_0201]  132.5 12.57 90 top
RC536  150_0201_1%  [R_0201]  145.75 6.7 180 top
RC537  1.5K_0201_5%  [R_0201]  144.22 10.14 180 top
RC538  1.5K_0201_5%  [R_0201]  136.75 11.13 0 top
RC539  0_0201_5%  [R0201_0OHM]  155.15 32.68 0 bottom
RC540  0_0201_5%  [R0201_0OHM]  155.15 33.23 0 bottom
RC546  49.9_0201_1%  [R_0201]  166.87 38.79 270 top
RC547  0_0201_5%  [R_0201]  182.9 33.69 180 bottom
RC548  1K_0201_1%  [R_0201]  171.46 33.02 90 bottom
RC550  10K_01005_1%  [R_01005]  141.45 56.64 180 top
RC553  100K_01005_1%  [R_01005]  143.85 52.17 90 top
RC554  1K_0201_5%  [R_0201]  151 32.87 0 bottom
RC555  15_0201_1%  [R_0201]  131.09 59.08 180 bottom
RC556  0_0201_5%  [R0201_0OHM]  55.61 24.54 180 top
RC561  0_0402_5%  [R_0402]  39.8 10.6 90 top
RC562  0_0402_5%  [R0402_0OHM]  40.58 10.6 90 top
RC563  10K_01005_1%  [R_01005]  141.45 56.19 180 top
RC564  10K_01005_1%  [R_01005]  132.27 42.98 0 bottom
RC565  100K_01005_1%  [R_01005]  140.09 49.18 0 top
RC566  100K_01005_1%  [R_01005]  139.77 49.72 0 top
RC567  10K_01005_1%  [R_01005]  132.3 49.39 0 bottom
RC568  100K_01005_1%  [R_01005]  131.09 49.39 0 bottom
RC569  100K_01005_1%  [R_01005]  142.58 57.85 90 top
RC570  10K_01005_1%  [R_01005]  118.45 74.89 180 bottom
RC571  10K_01005_1%  [R_01005]  133.84 65.76 180 top
RC572  10K_01005_1%  [R_01005]  139.57 41.96 0 top
RC573  10K_01005_1%  [R_01005]  139.99 41.52 0 top
RC574  10K_0201_5%  [R_0201]  129.17 44.01 270 bottom
RC575  10K_0201_5%  [R_0201]  127.27 46.97 90 bottom
RC576  1M_0201_5%  [R_0201]  146.19 54.49 180 top
RD1  240_0201_1%  [R_0201]  197.71 59.75 0 bottom
RD2  240_0201_1%  [R_0201]  175.38 76.72 90 bottom
RD3  240_0201_1%  [R_0201]  197.71 60.31 0 bottom
RD4  240_0201_1%  [R_0201]  174.82 76.72 90 bottom
RD5  240_0201_1%  [R_0201]  154.79 76.74 90 bottom
RD6  240_0201_1%  [R_0201]  139.44 76.67 90 bottom
RD7  240_0201_1%  [R_0201]  154.23 76.74 90 bottom
RD8  240_0201_1%  [R_0201]  138.88 76.67 90 bottom
RD10  8.2K_0201_1%  [R_0201]  182.48 62.97 180 bottom
RD11  10_0201_1%  [R_0201]  178.47 61.39 90 bottom
RD12  8.2K_0201_1%  [R_0201]  181.9 61.85 0 bottom
RD13  24.9_0201_1%  [R_0201]  180.24 61.38 0 bottom
RD21  8.2K_0201_1%  [R_0201]  162.45 62.96 180 bottom
RD22  10_0201_1%  [R_0201]  176.79 61.39 90 bottom
RD23  8.2K_0201_1%  [R_0201]  151.66 63.53 0 bottom
RD24  24.9_0201_1%  [R_0201]  177.91 61.97 270 bottom
RD25  4.99_0201_1%  [R_0201]  176 60.48 90 bottom
RD26  24.9_0201_1%  [R_0201]  174.89 61.06 270 bottom
RD27  8.2K_0201_1%  [R_0201]  186.46 77.31 270 bottom
RD28  8.2K_0201_1%  [R_0201]  187.01 76.72 90 bottom
RD29  68_0201_1%  [R_0201]  197.71 51.4 0 bottom
RD30  68_0201_1%  [R_0201]  161.95 76.74 90 bottom
RD31  68_0201_1%  [R_0201]  197.71 56.96 0 bottom
RD32  68_0201_1%  [R_0201]  157.58 76.74 90 bottom
RD33  68_0201_1%  [R_0201]  197.71 58.07 0 bottom
RD34  68_0201_1%  [R_0201]  156.46 76.74 90 bottom
RD35  68_0201_1%  [R_0201]  197.71 57.52 0 bottom
RD36  68_0201_1%  [R_0201]  157.02 76.74 90 bottom
RD37  68_0201_1%  [R_0201]  197.71 58.63 0 bottom
RD38  68_0201_1%  [R_0201]  155.91 76.74 90 bottom
RD39  68_0201_1%  [R_0201]  197.71 59.19 0 bottom
RD40  68_0201_1%  [R_0201]  155.35 76.74 90 bottom
RD41  68_0201_1%  [R_0201]  184.78 76.72 90 bottom
RD42  68_0201_1%  [R_0201]  148.94 76.67 90 bottom
RD43  68_0201_1%  [R_0201]  184.22 76.72 90 bottom
RD44  68_0201_1%  [R_0201]  147.82 76.67 90 bottom
RD45  68_0201_1%  [R_0201]  183.1 76.72 90 bottom
RD46  68_0201_1%  [R_0201]  146.71 76.67 90 bottom
RD47  68_0201_1%  [R_0201]  183.66 76.72 90 bottom
RD48  68_0201_1%  [R_0201]  148.38 76.67 90 bottom
RD49  68_0201_1%  [R_0201]  182.54 76.72 90 bottom
RD50  68_0201_1%  [R_0201]  147.26 76.67 90 bottom
RD51  68_0201_1%  [R_0201]  178.17 76.72 90 bottom
RD52  68_0201_1%  [R_0201]  142.24 76.67 90 bottom
RD53  68_0201_1%  [R_0201]  177.05 76.72 90 bottom
RD54  68_0201_1%  [R_0201]  141.12 76.67 90 bottom
RD55  68_0201_1%  [R_0201]  177.61 76.72 90 bottom
RD56  68_0201_1%  [R_0201]  141.68 76.67 90 bottom
RD57  68_0201_1%  [R_0201]  176.5 76.72 90 bottom
RD58  68_0201_1%  [R_0201]  140.56 76.67 90 bottom
RD59  68_0201_1%  [R_0201]  175.94 76.72 90 bottom
RD60  68_0201_1%  [R_0201]  140 76.67 90 bottom
RD61  80.6_0201_1%  [R_0201]  189.77 62.16 270 bottom
RD62  80.6_0201_1%  [R_0201]  152.24 74.15 180 bottom
RD63  68_0201_1%  [R_0201]  197.71 51.96 0 bottom
RD64  80.6_0201_1%  [R_0201]  187.95 62.16 270 bottom
RD65  80.6_0201_1%  [R_0201]  197.71 53.43 0 bottom
RD66  80.6_0201_1%  [R_0201]  160.27 76.74 90 bottom
RD67  80.6_0201_1%  [R_0201]  197.71 52.88 0 bottom
RD68  80.6_0201_1%  [R_0201]  160.83 76.74 90 bottom
RD69  80.6_0201_1%  [R_0201]  180.87 76.72 90 bottom
RD70  80.6_0201_1%  [R_0201]  144.72 76.67 90 bottom
RD71  68_0201_1%  [R_0201]  162.5 76.74 90 bottom
RD72  80.6_0201_1%  [R_0201]  145.28 76.67 90 bottom
RD73  80.6_0201_1%  [R_0201]  187.39 62.16 270 bottom
RD74  68_0201_1%  [R_0201]  163.06 76.74 90 bottom
RD75  68_0201_1%  [R_0201]  197.71 50.28 0 bottom
RD76  37.4_0201_1%  [R_0201]  159.15 76.74 90 bottom
RD77  68_0201_1%  [R_0201]  197.71 50.84 0 bottom
RD78  37.4_0201_1%  [R_0201]  197.71 53.99 0 bottom
RD79  37.4_0201_1%  [R_0201]  197.71 54.55 0 bottom
RD80  80.6_0201_1%  [R_0201]  181.43 76.72 90 bottom
RD81  37.4_0201_1%  [R_0201]  180.31 76.72 90 bottom
RD82  37.4_0201_1%  [R_0201]  144.17 76.67 90 bottom
RD83  68_0201_1%  [R_0201]  164.18 76.74 90 bottom
RD84  37.4_0201_1%  [R_0201]  179.75 76.72 90 bottom
RD85  68_0201_1%  [R_0201]  163.62 76.74 90 bottom
RD86  37.4_0201_1%  [R_0201]  143.61 76.67 90 bottom
RD87  80.6_0201_1%  [R_0201]  152.24 74.71 180 bottom
RD88  68_0201_1%  [R_0201]  197.71 49.73 0 bottom
RD89  80.6_0201_1%  [R_0201]  152.24 72.47 180 bottom
RD90  37.4_0201_1%  [R_0201]  159.71 76.74 90 bottom
RE1  100K_0201_1%  [R_0201]  49.38 16.28 90 top
RE2  100K_0201_1%  [R_0201]  48.1 17.49 90 top
RE3  100K_0201_1%  [R_0201]  47.48 16.36 90 top
RE4  100K_0201_1%  [R_0201]  47.4 17.56 90 top
RE5  0_0402_5%  [R0402_0OHM]  54.08 33.14 180 top
RE6  0_0402_5%  [R0402_0OHM]  38.46 19.35 0 top
RE7  0_0402_5%  [R0402_0OHM]  53.52 20.54 180 top
RE8  4.7K_0201_5%  [R_0201]  52.73 25.11 0 top
RE9  4.7K_0201_5%  [R_0201]  53.9 25.41 90 top
RE12  100K_0201_5%  [R_0201]  45.28 16.4 180 top
RE16  10K_0201_5%  [R_0201]  39.34 30.42 180 top
RE17  10K_0201_5%  [R_0201]  52.5 26.45 0 top
RE18  100K_0201_5%  [R_0201]  43.04 32.51 270 top
RE19  100K_0201_5%  [R_0201]  51.21 16.75 180 top
RE20  100K_0201_5%  [R_0201]  37.7 20.04 180 top
RE21  100K_0201_5%  [R_0201]  38.75 29.19 0 top
RE22  100K_0201_5%  [R_0201]  41.01 17.83 90 top
RE23  100K_0201_5%  [R_0201]  37.76 30.89 180 top
RE25  100_0201_5%  [R_0201]  36.53 20.13 180 top
RE26  100K_0201_5%  [R_0201]  55.62 26.27 180 top
RE27  43_0402_1%  [R_0402]  46.81 31.83 90 top
RE28  100K_0201_5%  [R_0201]  48.43 32.37 270 top
RE29  0_0201_5%  [R0201_0OHM]  40.44 17.81 270 top
RE30  1K_0201_5%  [R_0201]  38.4 17.83 0 top
RE31  100K_0201_5%  [R_0201]  39.38 20.94 180 top
RE32  100K_0201_5%  [R_0201]  40.19 18.41 180 top
RE45  100K_0201_5%  [R_0201]  56.6 23.44 180 top
RE46  300_0201_1%  [R_0201]  46.65 16.95 270 top
RE47  300_0201_1%  [R_0201]  45.88 16.94 270 top
RE48  49.9_0402_1%  [R_0402]  32.75 7.26 180 top
RE49  10K_0201_5%  [R_0201]  33.99 6.76 90 top
RE50  100K_0201_5%  [R_0201]  35.33 6.74 90 top
RE51  10K_0402_5%  [R_0402]  47.66 34.42 270 top
RE57  10K_0201_5%  [R_0201]  34.75 6.74 90 top
RE58  100K_0201_5%  [R_0201]  54.44 23.55 180 top
RE66  10K_0201_5%  [R_0201]  54.95 28.47 180 top
RE67  10K_0201_5%  [R_0201]  53.37 27.02 180 top
RE68  10K_0201_5%  [R_0201]  55.24 26.84 180 top
RE69  10K_0201_5%  [R_0201]  53.36 29.38 180 top
RE70  10K_0201_5%  [R_0201]  54.95 29.05 180 top
RE71  10K_0201_5%  [R_0201]  53.36 28.8 180 top
RE72  10K_0201_5%  [R_0201]  50.26 32.37 270 top
RE73  10K_0201_5%  [R_0201]  50.87 32.37 270 top
RE74  100K_0201_5%  [R_0201]  53.36 28.21 180 top
RE75  100K_0201_5%  [R_0201]  38.89 27.28 0 top
RE76  100K_0201_5%  [R_0201]  44.94 34.78 0 top
RE77  100K_0201_5%  [R_0201]  43.61 32.46 270 top
RE78  100K_0201_5%  [R_0201]  51.48 32.37 270 top
RE79  100K_0201_5%  [R_0201]  50.97 33.61 180 top
RE80  100K_0201_5%  [R_0201]  49.04 32.37 270 top
RE81  100K_0201_5%  [R_0201]  49.65 32.37 270 top
RE82  100K_0201_5%  [R_0201]  42.32 34.16 270 top
RE83  100K_0201_5%  [R_0201]  45.27 17.81 270 top
RE84  100K_0201_5%  [R_0201]  41.76 34.16 270 top
RE85  100K_0201_5%  [R_0201]  42.46 32.65 270 top
RE86  100K_0201_5%  [R_0201]  42.97 34.31 270 top
RE87  100K_0201_5%  [R_0201]  53.36 27.58 180 top
RE88  100K_0201_5%  [R_0201]  51.76 17.36 90 top
RE89  100K_0201_5%  [R_0201]  38.75 29.84 0 top
RE90  10K_0201_5%  [R_0201]  39.47 26.72 180 top
RE91  10K_0201_5%  [R_0201]  39.47 24.79 180 top
RE92  10K_0201_5%  [R_0201]  33.42 6.76 90 top
RE93  10K_0201_5%  [R_0201]  39.46 25.36 180 top
RE97  100K_0201_5%  [R_0201]  60.05 30.22 180 top
RE98  1M_0201_5%  [R_0201]  62.38 30.21 0 top
RE99  332K_0402_1%  [R_0402]  60.72 30.31 0 top
RE100  2.2K_0201_5%  [R_0201]  37 32.63 180 top
RE101  2.2K_0201_5%  [R_0201]  40.3 31.71 90 top
RE155  10K_0201_5%  [R_0201]  39 28.05 180 top
RE161  10K_0201_1%  [R_0201]  3.9 75.88 90 bottom
RE163  10K_0201_5%  [R_0201]  38.29 22.85 0 top
RE165  0_0201_5%  [R0201_0OHM]  127.85 48.75 180 bottom
RE177  100K_0201_5%  [R_0201]  60.45 17.17 90 top
RE182  0_0201_5%  [R0201_0OHM]  127.27 49.31 0 bottom
RE213  100_0201_5%  [R_0201]  60.08 15.22 180 top
RE473  100K_0201_5%  [R_0201]  127.27 48.16 0 bottom
RE477  0_0201_5%  [R0201_0OHM]  63.24 17.3 270 top
RE478  100K_0201_5%  [R_0201]  55.46 17.02 90 top
RE479  100K_0201_5%  [R_0201]  38.13 21.57 180 top
RE507  0_0201_5%  [R0201_0OHM]  127.85 49.86 180 bottom
RE508  0_0201_5%  [R0201_0OHM]  63.17 18.47 270 top
RE509  0_0201_5%  [R0201_0OHM]  64.42 17.9 90 top
RE510  10K_0201_5%  [R_0201]  63.8 17.89 90 top
RE511  100K_0201_5%  [R_0201]  64.43 23.85 180 top
RE512  0_0201_5%  [R0201_0OHM]  49.95 16.86 270 top
RE513  0_0201_5%  [R0201_0OHM]  42.24 18 270 top
RE516  100K_0201_5%  [R_0201]  55.62 25.11 180 top
RE524  10K_0201_5%  [R_0201]  36.73 6.74 90 top
RE525  0_0201_5%  [R0201_0OHM]  36.15 7.32 270 top
RE526  100K_0201_5%  [R_0201]  44.85 34.17 270 top
RE527  100_0201_1%  [R_0201]  45.47 33.59 90 top
RE529  4.7K_0402_5%  [R_0402]  48.46 34.41 270 top
RE530  0_0201_5%  [R0201_0OHM]  36.4 32.02 0 top
RE531  0_0201_5%  [R0201_0OHM]  39.7 32.29 270 top
RE532  0_0201_5%  [R0201_0OHM]  38.75 23.42 180 top
RE533  0_0201_5%  [R0201_0OHM]  39.38 21.5 180 top
RE534  0_0201_5%  [R_0201]  52.55 22.42 0 top
RE535  0_0201_5%  [R0201_0OHM]  51.17 17.38 90 top
RE536  0_0201_5%  [R_0201]  55.62 25.68 180 top
RE537  0_0201_5%  [R0201_0OHM]  49.78 33.66 90 top
RE538  0_0201_5%  [R0201_0OHM]  44.89 31.75 90 top
RE541  100K_0201_5%  [R_0201]  50.31 18.34 270 top
RE542  100K_0201_5%  [R_0201]  40.87 31.67 90 top
RE543  0_0201_5%  [R0201_0OHM]  41.44 31.66 90 top
RE544  100K_0201_5%  [R_0201]  63.85 23.25 0 top
RE545  100K_0201_5%  [R_0201]  38.54 23.98 0 top
RE546  100K_0201_5%  [R_0201]  38.39 18.68 0 top
RE547  100_0201_5%  [R_0201]  56.78 25.92 90 top
RE548  0_0201_5%  [R0201_0OHM]  53.13 16.05 0 top
RE549  0_0201_5%  [R_0201]  53.13 16.62 0 top
RE550  0_0201_5%  [R0201_0OHM]  40.98 16.01 270 top
RE551  0_0201_5%  [R0201_0OHM]  38.28 6.1 180 top
RE552  0_0201_5%  [R_0201]  31.94 18.11 270 top
RE553  0_0201_5%  [R_0201]  32.55 18.11 270 top
RE554  0_0201_5%  [R_0201]  35.18 21.22 180 top
RFP7  0_0201_5%  [R_0201]  94.77 12.49 180 bottom
RFP8  0_0201_5%  [R_0201]  94.77 13.04 180 bottom
RI1  6.2_0402_5%  [R_0402]  17.72 43.75 180 top
RI2  6.2_0402_5%  [R_0402]  17.72 42.89 180 top
RI3  150_0402_5%  [R_0402]  15.41 44.59 270 top
RI4  150_0402_5%  [R_0402]  15.41 42.97 270 top
RI5  6.2_0402_5%  [R_0402]  17.72 44.52 180 top
RI6  6.2_0402_5%  [R_0402]  17.72 42.13 180 top
RI7  6.2_0402_5%  [R_0402]  17.72 38.88 180 top
RI8  6.2_0402_5%  [R_0402]  17.72 40.5 180 top
RI9  150_0402_5%  [R_0402]  15.41 39.71 270 top
RI10  150_0402_5%  [R_0402]  15.41 41.34 270 top
RI11  6.2_0402_5%  [R_0402]  17.72 39.64 180 top
RI12  6.2_0402_5%  [R_0402]  17.72 41.26 180 top
RI55  0_0201_5%  [R0201_0OHM]  138.71 57.9 180 top
RIO3  0_0201_5%  [R_0201-NPM]  192.06 17.52 0 top
RIO4  0_0201_5%  [R_0201-NPM]  192.06 16.78 0 top
RIO5  0_0201_5%  [R_0201-NPM]  192.09 18.29 0 top
RIO6  0_0201_5%  [R_0201-NPM]  192.06 18.98 0 top
RM1  0_0402_5%  [R0402_0OHM]  26.08 35.42 0 top
RM2  0_0402_5%  [R0402_0OHM]  14.12 54.92 90 top
RM3  2.2K_01005_5%  [R_01005]  24.84 36.99 180 top
RM4  2.2K_01005_5%  [R_01005]  23.68 36.99 0 top
RM5  0_01005_5%  [R_01005]  21.36 43.39 0 bottom
RM6  0_01005_5%  [R_01005]  28.11 39.27 0 top
RM7  10.2K_0201_1%  [R_0201]  28.25 35.65 270 top
RM10  1K_01005_1%  [R_01005]  21.07 36.7 270 top
RM11  4.7K_01005_5%  [R_01005]  22.41 35.98 90 top
RM12  4.7K_01005_5%  [R_01005]  21.75 35.98 90 top
RM13  4.99K_01005_1%  [R_01005]  23.3 47.04 90 top
RM14  4.7K_01005_5%  [R_01005]  22.43 37.39 270 top
RM15  4.7K_01005_5%  [R_01005]  21.77 37.39 270 top
RM16  10K_01005_1%  [R_01005]  21.72 43.84 180 bottom
RM17  20K_01005_1%  [R_01005]  21.72 42.47 180 bottom
RM23  4.7K_01005_5%  [R_01005]  15.52 52.99 180 top
RM26  4.7K_01005_5%  [R_01005]  22.59 47.05 90 top
RM27  4.7K_01005_5%  [R_01005]  21.93 47.05 90 top
RM28  4.7K_01005_5%  [R_01005]  20.85 46.85 90 top
RM30  15_01005_1%  [R_01005]  21.47 47.4 270 top
RM31  0_0201_5%  [R0201_0OHM]  15.56 72.49 180 top
RM32  0_0201_5%  [R0201_0OHM]  20.31 76.14 270 top
RM33  0_0201_5%  [R0201_0OHM]  14.72 74.92 0 top
RM34  0_0201_5%  [R0201_0OHM]  19.76 75.55 90 top
RM35  0_0201_5%  [R0201_0OHM]  19.2 76.14 270 top
RM36  0_0201_5%  [R0201_0OHM]  14.97 73.6 0 top
RM37  0_0201_5%  [R0201_0OHM]  15.56 73.04 180 top
RM38  0_0201_5%  [R0201_0OHM]  15.48 74.28 180 top
RM39  5.1K_0201_1%  [R_0201]  27.69 36.53 270 top
RM40  4.7K_01005_5%  [R_01005]  24.89 40.84 0 bottom
RM41  4.7K_01005_5%  [R_01005]  25.25 40.38 180 bottom
RM42  4.7K_01005_5%  [R_01005]  24.89 41.75 0 bottom
RM43  4.7K_01005_5%  [R_01005]  25.25 41.29 180 bottom
RM44  4.7K_01005_5%  [R_01005]  21.79 41.99 180 bottom
RM45  4.7K_01005_5%  [R_01005]  23.23 36.21 90 top
RM46  4.7K_01005_5%  [R_01005]  21.36 41.56 0 bottom
RM47  4.7K_01005_5%  [R_01005]  23.23 37.05 180 top
RM48  100K_0201_5%  [R_0201]  23.84 36.16 0 top
RM49  100K_0201_5%  [R_0201]  25.24 38.31 270 bottom
RM50  4.7K_01005_5%  [R_01005]  21.31 35.58 180 top
RM51  4.7K_0201_5%  [R_0201]  21.66 35.06 180 top
RM52  0_0201_5%  [R0201_0OHM]  28.99 40.26 180 top
RM53  0_0201_5%  [R0201_0OHM]  28.99 40.82 180 top
RM54  0_0201_5%  [R0201_0OHM]  28.99 41.94 180 top
RM55  0_0201_5%  [R0201_0OHM]  28.99 41.38 180 top
RM56  0_0201_5%  [R0201_0OHM]  28.99 43.06 180 top
RM57  0_0201_5%  [R0201_0OHM]  28.99 42.5 180 top
RM58  0_0201_5%  [R0201_0OHM]  28.99 44.18 180 top
RM59  0_0201_5%  [R0201_0OHM]  28.99 43.62 180 top
RM60  0_01005_5%  [R01005_0OHM]  18.73 38.18 270 top
RM61  0_0201_5%  [R0201_0OHM]  21.86 46.99 180 bottom
RN3  10K_0201_5%  [R_0201]  55.8 37.8 270 top
RN7  10K_0201_5%  [R_0201]  64.85 51.37 180 top
RN10  0_0201_5%  [R0201_0OHM]  49.05 50.75 90 top
RN17  0_0402_5%  [R_0402]  51.63 53.83 90 top
RN18  0_0402_5%  [R_0402]  52.39 53.83 90 top
RN67  0_0201_5%  [R_0201]  36.41 67.94 0 bottom
RN73  0_0201_5%  [R0201_0OHM]  47.02 61.29 270 bottom
RN74  10K_0201_5%  [R_0201]  58.34 43.11 180 top
RN80  0_0201_5%  [R0201_0OHM]  60.64 41.68 270 top
RN81  0_0201_5%  [R0201_0OHM]  57.76 42.52 0 top
RN82  0_0201_5%  [R_0201]  59.54 42.52 180 top
RN84  0_0402_5%  [R0402_0OHM]  54.29 44.1 0 top
RN85  10K_0201_5%  [R_0201]  54.23 45.57 0 top
RN86  0_0201_5%  [R0201_0OHM]  55.42 45.82 90 top
RN87  0_0201_5%  [R0201_0OHM]  53.42 49.74 270 top
RN88  100K_0201_5%  [R_0201]  52.83 49.15 90 top
RN89  100K_0201_5%  [R_0201]  56.51 39.83 90 top
RN90  0_0201_5%  [R0201_0OHM]  57.07 42.52 180 top
RN91  10K_0201_5%  [R_0201]  56.49 43.13 0 top
RN92  10K_0201_5%  [R_0201]  55.84 38.44 90 top
RN95  10K_0201_5%  [R_0201]  58.61 38.39 90 top
RN96  0_0201_5%  [R0201_0OHM]  58.6 37.72 270 top
RN97  10K_0201_5%  [R_0201]  56 46.59 90 top
RN112  0_0201_5%  [R_0201]  59.54 43.11 180 top
RN113  0_0201_5%  [R_0201]  54 49.74 270 top
RN115  0_0402_5%  [R_0402]  55.4 57.66 270 top
RN116  0_0402_5%  [R_0402]  54.61 57.66 270 top
RN117  0_0402_5%  [R_0402]  53.16 53.83 90 top
RN118  0_0402_5%  [R_0402]  53.92 53.83 90 top
RN192  0_0201_5%  [R_0201]  58.44 49.69 270 top
RN193  0_0201_5%  [R0201_0OHM]  48.44 51.34 270 top
RN196  100K_0201_5%  [R_0201]  26.88 5.74 270 top
RN197  82K_0201_1%  [R_0201]  26.93 6.91 270 top
RN198  10K_0201_5%  [R_0201]  30.8 6.62 270 top
RN199  100K_0201_5%  [R_0201]  48.18 60.71 90 bottom
RPD11  3.3K_01005_1%  [R_01005]  15.98 27.66 90 top
RPD12  3.3K_01005_1%  [R_01005]  17.28 27.63 90 top
RPD13  3.3K_01005_1%  [R_01005]  16.59 37.84 0 top
RPD14  3.3K_01005_1%  [R_01005]  18.49 27.6 90 top
RPD17  0_01005_5%  [R01005_0OHM]  16.78 28.89 180 bottom
RPD21  0_01005_5%  [R01005_0OHM]  16.78 30.26 180 bottom
RPD22  0_01005_5%  [R01005_0OHM]  16.42 30.84 180 bottom
RPD84  0_0402_5%  [R0402_0OHM]  29.18 34.29 180 bottom
RPD88  0_01005_5%  [R01005_0OHM]  19.35 36.32 90 bottom
RPD90  100K_01005_1%  [R_01005]  28.4 29.69 180 bottom
RPD91  300K_01005_1%  [R_01005]  28.75 32.6 270 bottom
RPD92  100K_01005_1%  [R_01005]  28.22 32.25 90 bottom
RPD100  100K_01005_1%  [R_01005]  28.04 29.23 0 bottom
RPD112  0_01005_5%  [R01005_0OHM]  16.42 31.48 180 bottom
RPD121  0_1206_5%  [R1206_0OHM]  28.67 39.1 270 bottom
RPD123  0_01005_5%  [R01005_0OHM]  16.32 34.81 0 bottom
RPD124  0_01005_5%  [R_01005]  23.71 26.48 90 bottom
RPD126  0_01005_5%  [R01005_0OHM]  16.42 29.34 0 bottom
RPD127  0_01005_5%  [R01005_0OHM]  16.32 33.89 0 bottom
RPD128  100K_01005_1%  [R_01005]  16.66 33.42 270 bottom
RPD129  10K_01005_1%  [R_01005]  16.2 33.42 270 bottom
RPD130  0_01005_5%  [R_01005]  18.82 36.68 270 bottom
RPD139  0_01005_5%  [R_01005]  21.09 36.32 90 bottom
RPD141  0_01005_5%  [R_01005]  16.78 29.8 180 bottom
RPD163  0_01005_5%  [R01005_0OHM]  18.98 27.03 270 bottom
RPD164  0_01005_5%  [R01005_0OHM]  18.31 27.03 270 bottom
RPD169  1M_01005_1%  [R_01005]  23.25 26.48 90 bottom
RPD170  10K_01005_1%  [R_01005]  22.8 26.48 90 bottom
RPD181  10K_01005_1%  [R_01005]  16.82 27.63 90 top
RPD187  0_01005_5%  [R01005_0OHM]  24.62 26.48 90 bottom
RPD190  100K_01005_1%  [R_01005]  24.17 26.83 270 bottom
RPD191  100K_01005_1%  [R_01005]  16.68 34.35 180 bottom
RPD204  0_01005_5%  [R_01005]  21.62 36.32 90 bottom
RPD205  15_01005_1%  [R_01005]  16.68 32.57 180 bottom
RR123  22_0201_5%  [R_0201]  3.72 24.79 180 bottom
RR124  22_0201_5%  [R_0201]  3.72 26.47 180 bottom
RR125  22_0201_5%  [R_0201]  3.99 20.65 180 bottom
RR126  22_0201_5%  [R_0201]  3.99 21.21 180 bottom
RR127  22_0201_5%  [R_0201]  3.99 22.88 180 bottom
RR132  49.9K_0201_1%  [R_0201]  3.17 24.21 0 bottom
RR144  0_0201_5%  [R0201_0OHM]  13.12 33.25 270 top
RR156  0_0201_5%  [R0201_0OHM]  15.35 22.5 0 top
RR161  49.9K_0201_1%  [R_0201]  3.14 25.35 0 bottom
RR162  49.9K_0201_1%  [R_0201]  3.14 25.91 0 bottom
RR163  49.9K_0201_1%  [R_0201]  3.41 20.09 0 bottom
RR164  49.9K_0201_1%  [R_0201]  3.41 21.77 0 bottom
RR165  49.9K_0201_1%  [R_0201]  3.41 22.33 0 bottom
RR166  0_0402_5%  [R0402_0OHM]  8.13 30.09 0 top
RR167  100K_0201_5%  [R_0201]  13.68 33.25 270 top
RS1  10K_0201_5%  [R_0201]  112.85 33.39 0 top
RS2  15K_0201_5%  [R_0201]  59.66 47.03 180 top
RS3  51_0201_5%  [R_0201]  59.03 48.47 270 top
RS4  0_0201_5%  [R0201_0OHM]  69.29 76.45 270 top
RS5  2.2K_0201_5%  [R_0201]  71.89 72.95 90 top
RS6  2.2K_0201_5%  [R_0201]  69.72 74.87 270 top
RS7  2.2K_0201_5%  [R_0201]  70.21 72.95 90 top
RS9  0_0201_5%  [R0201_0OHM]  72.71 75.5 180 top
RS10  0_0201_5%  [R0201_0OHM]  71.33 73.53 270 top
RS11  0_0201_5%  [R_0201]  70.28 74.29 90 top
RS12  0_0201_5%  [R_0201]  70.77 73.53 270 top
RS13  0_0201_5%  [R_0201]  24.5 76.07 0 top
RT1  3.3K_01005_1%  [R_01005]  38.46 53.37 270 top
RT2  2.2K_01005_1%  [R_01005]  31.63 53.32 270 top
RT3  2.2K_01005_1%  [R_01005]  32.42 53.32 270 top
RT4  3.3K_01005_1%  [R_01005]  32.95 53.32 270 top
RT5  10K_01005_1%  [R_01005]  23.08 51.97 270 top
RT6  10K_01005_1%  [R_01005]  22.62 51.97 270 top
RT7  10K_01005_1%  [R_01005]  22.16 51.97 270 top
RT8  10K_01005_1%  [R_01005]  21.71 51.97 270 top
RT9  0.01_0402_1%  [R_0402]  37.8 51.13 180 top
RT16  10K_01005_1%  [R_01005]  20.99 59.56 0 top
RT20  10K_01005_1%  [R_01005]  32.97 52.86 0 bottom
RT23  100K_01005_1%  [R_01005]  34.01 53.7 0 bottom
RT26  100K_01005_1%  [R_01005]  28.57 53.72 180 top
RT27  100K_01005_1%  [R_01005]  30.06 51.5 270 top
RT33  100K_01005_1%  [R_01005]  32.97 53.7 0 bottom
RT34  3.01K_01005_1%  [R_01005]  24.27 55.32 180 top
RT36  100_01005_1%  [R_01005]  28.68 51.5 270 top
RT39  4.75K_0201_0.5%  [R_0201]  29.32 55.96 0 top
RT40  0_0201_5%  [R_0201]  19.26 60.49 90 bottom
RT41  200_01005_1%  [R_01005]  20.69 57.98 0 top
